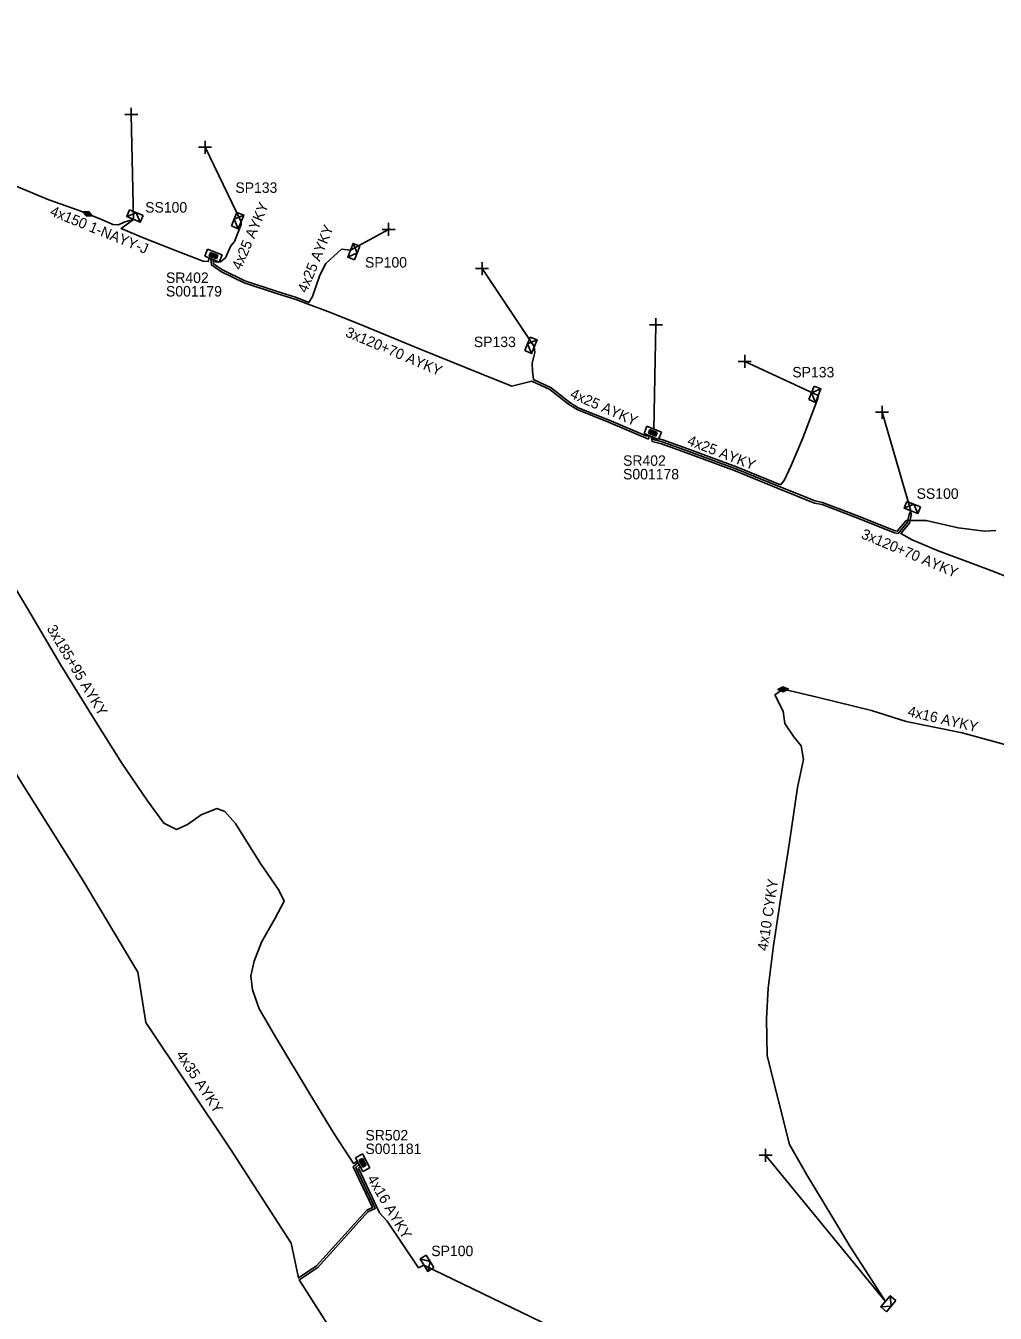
# Model space of a CAD drawing. Extents: x -763093 to -760976, y -1155572 to -1152009.
# Drawn here: x -761666.2 to -761573.4, y -1152391 to -1152267.8 of the extents above; entities that cross this region are included whole.
import ezdxf

# ---------------------------------------------------------------- set-up
doc = ezdxf.new("R2010")
doc.units = 0
for name, color, linetype in [('Vrstva 1', 7, 'Continuous'), ('Vrstva 19', 7, 'Continuous'), ('Vrstva 28', 7, 'Continuous'), ('Vrstva 29', 7, 'Continuous'), ('Vrstva 30', 7, 'Continuous'), ('Vrstva 31', 7, 'Continuous'), ('Vrstva 33', 7, 'Continuous'), ('Vrstva 34', 7, 'Continuous'), ('Vrstva 4', 7, 'Continuous'), ('Vrstva 5', 7, 'Continuous'), ('Vrstva 59', 7, 'Continuous'), ('Vrstva 6', 7, 'Continuous'), ('Vrstva 8', 7, 'Continuous'), ('Vrstva 9', 7, 'Continuous')]:
    doc.layers.add(name, color=color, linetype=linetype)

# ---------------------------------------------------------------- blocks, each defined once
blk = doc.blocks.new('NN870')
at = {"layer": 'Vrstva 4'}
for points in [[(0, -0.25), (0.5, 0), (0, 0.25), (-0.5, 0), (0, -0.25)], [(0.37, 0), (0, 0.19), (-0.36, 0), (0, -0.19), (0.37, 0)], [(0.24, 0), (0, 0.12), (-0.25, 0), (0, -0.12), (0.24, 0)], [(0.12, 0), (0, 0.06), (-0.13, 0), (0, -0.06), (0.12, 0)]]:
    blk.add_lwpolyline(points, dxfattribs=at)
blk = doc.blocks.new('NN800')
at = {"layer": 'Vrstva 1'}
for points in [[(-0.44, 0.44), (0.44, -0.44)], [(-0.44, -0.44), (0.44, 0.44)]]:
    blk.add_lwpolyline(points, dxfattribs=at)
blk = doc.blocks.new('NN620')
at = {"layer": 'Vrstva 8'}
for points in [[(0.75, 0), (-0.75, 0)], [(-0.75, 0), (-0.75, -0.75)], [(0.75, -0.75), (0.75, 0)], [(-0.75, -0.75), (0.75, -0.75)], [(0.37, -0.18), (-0.38, -0.18)], [(-0.38, -0.18), (-0.38, -0.56)], [(-0.38, -0.56), (0.37, -0.56)], [(0.32, -0.23), (-0.33, -0.23)], [(-0.33, -0.23), (-0.33, -0.51)], [(-0.33, -0.51), (0.32, -0.51)], [(0.27, -0.27), (-0.28, -0.27)], [(-0.28, -0.27), (-0.28, -0.46)], [(-0.28, -0.46), (0.27, -0.46)], [(0.23, -0.32), (-0.23, -0.32)], [(-0.23, -0.32), (-0.23, -0.42)], [(-0.23, -0.42), (0.23, -0.42)], [(-0.19, -0.37), (0.19, -0.37)], [(0.23, -0.42), (0.23, -0.32)], [(0.27, -0.46), (0.27, -0.27)], [(0.32, -0.51), (0.32, -0.23)], [(0.37, -0.56), (0.37, -0.18)]]:
    blk.add_lwpolyline(points, dxfattribs=at)
blk = doc.blocks.new('NN630')
at = {"layer": 'Vrstva 9'}
for points in [[(0, -0.7), (-0.7, 0)], [(-0.7, -0.7), (-0.7, 0), (0.7, 0), (0.7, -0.7)], [(-0.7, -0.7), (0.7, -0.7)], [(0, -0.7), (0.7, 0)]]:
    blk.add_lwpolyline(points, dxfattribs=at)

msp = doc.modelspace()

# ---------------------------------------------------------------- linework, layer by layer
at = {"layer": 'Vrstva 5'}
for points in [[(-761660.25, -1152285.76), (-761661.13, -1152285.42), (-761663.93, -1152284.42), (-761667.23, -1152283.04), (-761670.12, -1152281.75), (-761674.31, -1152280.06), (-761679.7, -1152277.9), (-761684.72, -1152276.28), (-761689.26, -1152274.88), (-761691.3, -1152274.22), (-761696.12, -1152272.01), (-761698.99, -1152270.39), (-761699.89, -1152269.51), (-761699.98, -1152268.24), (-761700.03, -1152267.76)], [(-761655.85, -1152286.3), (-761656.32, -1152286.44), (-761656.75, -1152286.57), (-761657.28, -1152286.8), (-761657.82, -1152286.77), (-761658.75, -1152286.37), (-761660.25, -1152285.76)], [(-761648.6, -1152289.99), (-761648.69, -1152290.32), (-761649.19, -1152290.28), (-761651.67, -1152289.32), (-761654.97, -1152288.01), (-761657.03, -1152287.15), (-761655.85, -1152286.3)], [(-761648.05, -1152290.21), (-761648.03, -1152290.36), (-761647.51, -1152290.35), (-761647.03, -1152289.98), (-761646.55, -1152288.83), (-761646.17, -1152288.41), (-761645.54, -1152286.78), (-761645.56, -1152286.53)], [(-761648.45, -1152290.06), (-761648.37, -1152290.65), (-761647.43, -1152291.3), (-761645.27, -1152292.36), (-761642.26, -1152293.34), (-761640.31, -1152293.96), (-761639.15, -1152294.41), (-761637.27, -1152295.11), (-761634.3, -1152296.29), (-761628.44, -1152298.7), (-761622.58, -1152301.07), (-761619.67, -1152302.24), (-761617.74, -1152301.76), (-761616.01, -1152302.58), (-761614.23, -1152303.96), (-761613.4, -1152304.49), (-761610.42, -1152305.69), (-761606.59, -1152307.32), (-761606.51, -1152306.98)], [(-761648.23, -1152290.14), (-761648.19, -1152290.53), (-761647.33, -1152291.12), (-761645.19, -1152292.18), (-761642.2, -1152293.16), (-761640.25, -1152293.78), (-761639.06, -1152294.23), (-761638.74, -1152293.67), (-761638.01, -1152291.62), (-761637.46, -1152290.5), (-761635.96, -1152289.15), (-761635.1, -1152289.24)], [(-761606.69, -1152306.91), (-761606.73, -1152307.05), (-761610.34, -1152305.51), (-761613.3, -1152304.31), (-761614.11, -1152303.8), (-761615.91, -1152302.4), (-761617.58, -1152301.61), (-761617.68, -1152300.82), (-761617.71, -1152300.04), (-761617.46, -1152299.04), (-761617.51, -1152298.46)], [(-761605.68, -1152307.27), (-761605.23, -1152307.38), (-761602.81, -1152308.24), (-761598.16, -1152309.96), (-761593.97, -1152311.69), (-761593.62, -1152311.27), (-761592.95, -1152309.85), (-761591.87, -1152307.29), (-761590.39, -1152303.43), (-761590.35, -1152303.15)], [(-761606.32, -1152307.06), (-761606.23, -1152307.53), (-761605.35, -1152307.76), (-761602.95, -1152308.62), (-761598.3, -1152310.34), (-761594.18, -1152312.03), (-761590.7, -1152313.43), (-761589.99, -1152313.57), (-761586.82, -1152314.77), (-761583.05, -1152316.3), (-761582.7, -1152316.34), (-761581.82, -1152315.27), (-761581.66, -1152314.53), (-761581.48, -1152314.19), (-761581.46, -1152314.58), (-761581.63, -1152315.36), (-761582.45, -1152316.35), (-761581.38, -1152316.96), (-761578.87, -1152318.01), (-761576.56, -1152318.88), (-761573.74, -1152319.93), (-761568.45, -1152322.04)], [(-761606.14, -1152307.14), (-761606.11, -1152307.36), (-761605.29, -1152307.57), (-761602.88, -1152308.43), (-761598.23, -1152310.15), (-761594.1, -1152311.85), (-761590.64, -1152313.23), (-761589.93, -1152313.37), (-761586.74, -1152314.59), (-761582.99, -1152316.1), (-761582.79, -1152316.13), (-761581.94, -1152315.1), (-761580.04, -1152315.12), (-761576.98, -1152315.82), (-761574.46, -1152316.11), (-761573.36, -1152316.06)], [(-761634.44, -1152376.4), (-761634.8, -1152376.64), (-761636.65, -1152373.8), (-761639.05, -1152369.88), (-761642.18, -1152364.69), (-761643.83, -1152361.82), (-761644.45, -1152360.02), (-761644.62, -1152358.68), (-761644.3, -1152357.26), (-761643.61, -1152355.44), (-761642.31, -1152353.16), (-761641.44, -1152351.52), (-761641.95, -1152350.47), (-761643.77, -1152347.82), (-761646.1, -1152344.1), (-761647.12, -1152342.94), (-761647.86, -1152342.68), (-761649.38, -1152343.28), (-761650.67, -1152344.21), (-761651.72, -1152344.67), (-761652.94, -1152344.08), (-761654.51, -1152341.94), (-761656.95, -1152338.33), (-761659.7, -1152333.97), (-761662.81, -1152328.96), (-761665.98, -1152323.54), (-761669.44, -1152317.85)], [(-761583.92, -1152389.83), (-761585.52, -1152387.35), (-761587.34, -1152384.56), (-761588.94, -1152381.84), (-761591.43, -1152377.73), (-761593.1, -1152374.83), (-761595.25, -1152366.34), (-761595.29, -1152362.79), (-761595.13, -1152359.86), (-761594.62, -1152355.79), (-761593.86, -1152350.77), (-761593.11, -1152345.89), (-761592.32, -1152340.65), (-761591.77, -1152337.96), (-761591.97, -1152336.68), (-761592.68, -1152335.8), (-761593.55, -1152334.52), (-761593.69, -1152333.35), (-761594.49, -1152331.79), (-761593.71, -1152331.26)], [(-761571.57, -1152336.8), (-761576.57, -1152335.43), (-761581.93, -1152334.35), (-761585.27, -1152333.29), (-761590.33, -1152332.03), (-761593.71, -1152331.26)], [(-761634.35, -1152376.55), (-761634.84, -1152376.97), (-761632.99, -1152380.85), (-761633.54, -1152381.11), (-761638.35, -1152386.44), (-761640.07, -1152387.59), (-761640.77, -1152384.25), (-761646.56, -1152375.28), (-761654.67, -1152363.13), (-761655.44, -1152358.33), (-761660.7, -1152349.53), (-761666.67, -1152339.99), (-761669.92, -1152334.61), (-761672.1, -1152336.22)], [(-761636.56, -1152393.15), (-761640, -1152387.78), (-761638.21, -1152386.6), (-761633.42, -1152381.27), (-761632.73, -1152380.94), (-761634.59, -1152377.02), (-761634.26, -1152376.74)], [(-761634.13, -1152376.89), (-761634.34, -1152377.07), (-761632.31, -1152381.35), (-761631.58, -1152382.14), (-761628.57, -1152386.63), (-761628.07, -1152386.37)]]:
    msp.add_lwpolyline(points, dxfattribs=at)
at = {"layer": 'Vrstva 59'}
for points in [[(-761655.85, -1152286.3), (-761656.06, -1152276.25)], [(-761645.56, -1152286.53), (-761649, -1152279.38)], [(-761635.1, -1152289.24), (-761631.44, -1152287.25)], [(-761617.51, -1152298.46), (-761622.5, -1152291)], [(-761606.07, -1152306.41), (-761605.88, -1152296.38)], [(-761590.35, -1152303.15), (-761597.38, -1152299.88)], [(-761581.48, -1152314.19), (-761584.25, -1152304.75)], [(-761583.92, -1152389.83), (-761595.39, -1152375.84)], [(-761628.07, -1152386.37), (-761606.56, -1152396.75)]]:
    msp.add_lwpolyline(points, dxfattribs=at)

# ---------------------------------------------------------------- block references
at = {"layer": 'Vrstva 19'}
for p, rotation in [((-761660.25, -1152285.76), -21.63664172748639), ((-761593.71, -1152331.26), -177.1828195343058)]:
    msp.add_blockref('NN870', p, dxfattribs=dict(at, rotation=rotation))
at = {"layer": 'Vrstva 28'}
for p, rotation in [((-761648.34, -1152290.1), 158.23093339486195), ((-761606.32, -1152307.06), 158.23093339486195), ((-761634.26, -1152376.74), 118.19743556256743)]:
    msp.add_blockref('NN620', p, dxfattribs=dict(at, rotation=rotation))
at = {"layer": 'Vrstva 31'}
for p, rotation in [((-761655.85, -1152286.3), 157.2700882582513), ((-761645.56, -1152286.53), -111.76906670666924), ((-761635.1, -1152289.24), 68.23093335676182), ((-761617.51, -1152298.46), -111.7690666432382), ((-761590.35, -1152303.15), -111.76906669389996), ((-761581.48, -1152314.19), 158.23093326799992), ((-761628.07, -1152386.37), 121.44282774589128), ((-761583.92, -1152389.83), 49.77383888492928)]:
    msp.add_blockref('NN630', p, dxfattribs=dict(at, rotation=rotation))
at = {"layer": 'Vrstva 34'}
for p, rotation in [((-761656.06, -1152276.25), 45), ((-761649, -1152279.38), 45), ((-761631.44, -1152287.25), 44.99999995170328), ((-761622.5, -1152291), 45), ((-761605.88, -1152296.38), 45), ((-761597.38, -1152299.88), 45), ((-761584.25, -1152304.75), 45), ((-761595.39, -1152375.84), 45)]:
    msp.add_blockref('NN800', p, dxfattribs=dict(at, rotation=rotation))

# ---------------------------------------------------------------- texts
at = {"layer": 'Vrstva 29'}
for s, p in [('S001179', (-761652.74, -1152293.67)), ('S001178', (-761609.02, -1152311.17)), ('S001181', (-761633.66, -1152375.73))]:
    msp.add_text(s, height=1, dxfattribs=at).set_placement(p)
at = {"layer": 'Vrstva 30'}
for s, p in [('SR402', (-761652.74, -1152292.37)), ('SR402', (-761609.02, -1152309.87)), ('SR502', (-761633.66, -1152374.43))]:
    msp.add_text(s, height=1, dxfattribs=at).set_placement(p)
at = {"layer": 'Vrstva 33'}
for s, p in [('SP133', (-761646.1, -1152283.75)), ('SS100', (-761654.73, -1152285.64)), ('SP100', (-761633.7, -1152290.9)), ('SP133', (-761623.29, -1152298.51)), ('SP133', (-761592.83, -1152301.41)), ('SS100', (-761580.94, -1152313.03)), ('SP100', (-761627.36, -1152385.5))]:
    msp.add_text(s, height=1, dxfattribs=at).set_placement(p)
at = {"layer": 'Vrstva 6'}
for s, rotation, p in [('4x150 1-NAYY-J', 337.87, (-761663.91, -1152285.88)), ('4x25 AYKY', 66.813, (-761645.58, -1152291.21)), ('4x25 AYKY', 67.627, (-761639.28, -1152293.4)), ('3x120+70 AYKY', 337.011, (-761635.66, -1152297.45)), ('4x25 AYKY', 336.194, (-761614.17, -1152303.33)), ('4x25 AYKY', 338.799, (-761602.96, -1152307.83)), ('3x120+70 AYKY', 337.117, (-761586.32, -1152316.77)), ('3x185+95 AYKY', 300.851, (-761664.18, -1152325.45)), ('4x16 AYKY', 346.814, (-761581.86, -1152333.81)), ('4x10 CYKY', 81.404, (-761595.21, -1152356.33)), ('4x35 AYKY', 303.49, (-761651.82, -1152366.23)), ('4x16 AYKY', 300.735, (-761633.54, -1152378.09))]:
    msp.add_text(s, height=1, rotation=rotation, dxfattribs=at).set_placement(p)

doc.saveas('drawing.dxf')
